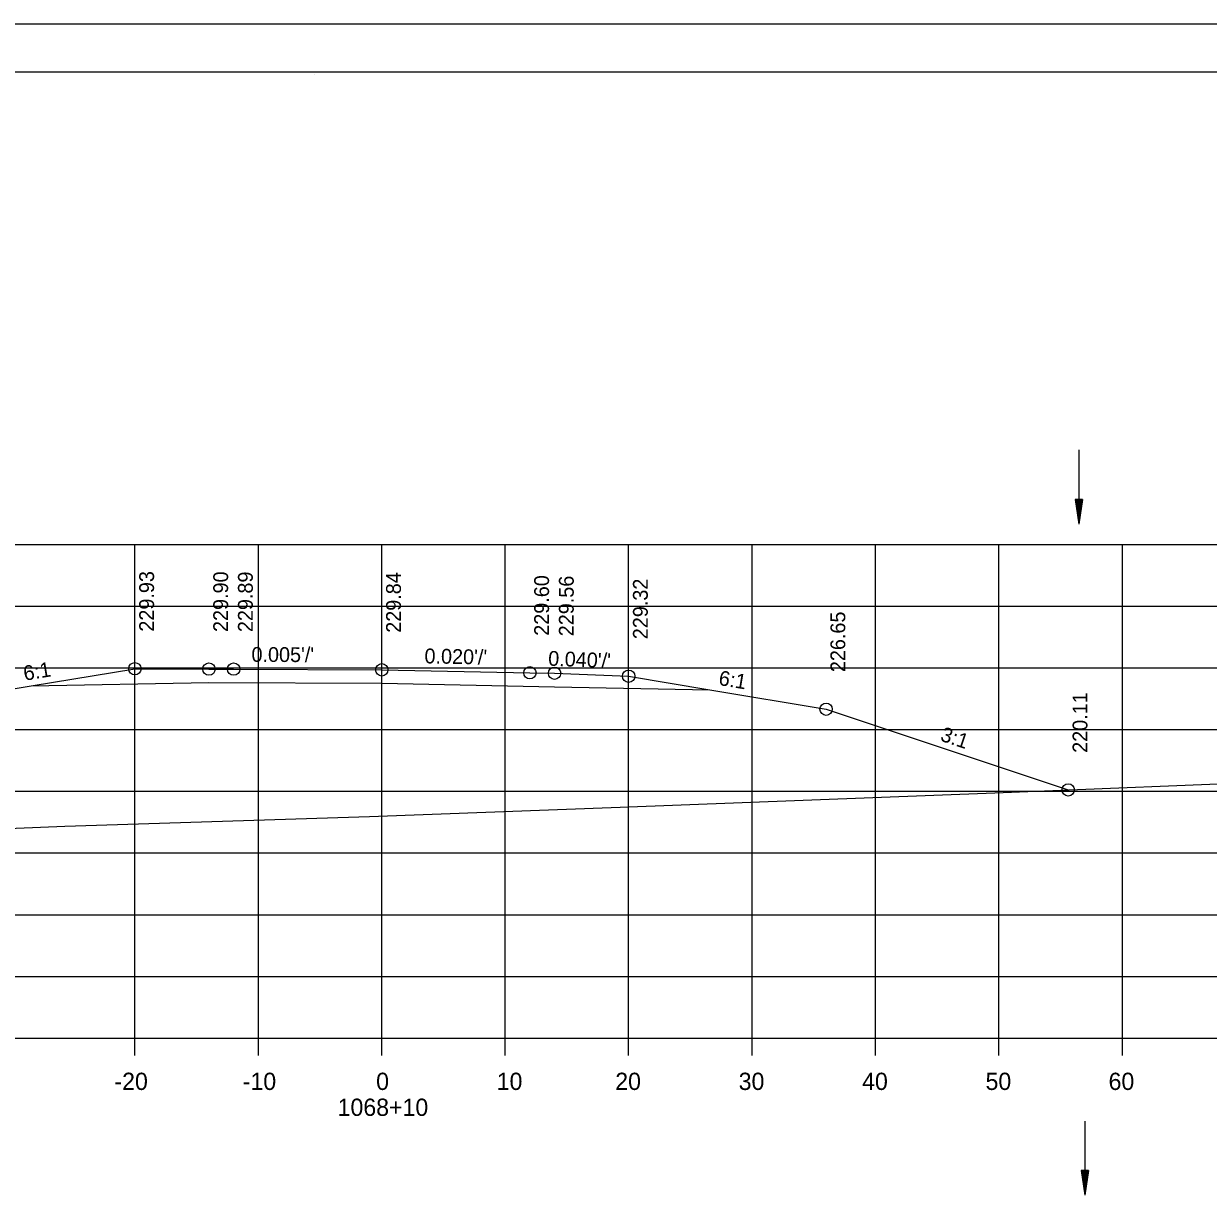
# Model space of a CAD drawing. Extents: x 1386544 to 1388153, y 379785 to 390999.
# Drawn here: x 1387330.7 to 1387426.6, y 389196.4 to 389292.2 of the extents above; entities that cross this region are included whole.
import ezdxf

# ---------------------------------------------------------------- set-up
doc = ezdxf.new("R2010")
doc.units = 0
for name, color, linetype in [('R_Alt Surface', 7, 'Continuous'), ('R_Axis', 7, 'Continuous'), ('R_Axis Annot', 7, 'Continuous'), ('R_Border', 7, 'Continuous'), ('R_Exist Surface', 7, 'Continuous'), ('R_Fin Surface', 7, 'Continuous'), ('R_Grid', 7, 'Continuous'), ('R_No Plot', 7, 'Continuous'), ('R_Water', 7, 'Continuous'), ('R_Xsect Elev', 7, 'Continuous'), ('R_Xsect Slope', 7, 'Continuous')]:
    doc.layers.add(name, color=color, linetype=linetype)

msp = doc.modelspace()

# ---------------------------------------------------------------- linework, layer by layer
at = {"layer": 'R_Alt Surface'}
msp.add_lwpolyline([(1387331.28, 389238.58), (1387345.676, 389238.868), (1387359.676, 389238.802), (1387373.676, 389238.522), (1387386.244, 389238.271)], dxfattribs=at)
at = {"layer": 'R_Axis'}
for p, q in [((1387209.676, 389210.047), (1387509.676, 389210.047)), ((1387339.676, 389208.647), (1387339.676, 389210.047)), ((1387349.676, 389208.647), (1387349.676, 389210.047)), ((1387359.676, 389208.647), (1387359.676, 389210.047)), ((1387369.676, 389208.647), (1387369.676, 389210.047)), ((1387379.676, 389208.647), (1387379.676, 389210.047)), ((1387389.676, 389208.647), (1387389.676, 389210.047)), ((1387399.676, 389208.647), (1387399.676, 389210.047)), ((1387409.676, 389208.647), (1387409.676, 389210.047)), ((1387419.676, 389208.647), (1387419.676, 389210.047))]:
    msp.add_line(p, q, dxfattribs=at)
at = {"layer": 'R_Border'}
for p, q in [((1387201.676, 389288.341), (1387517.856, 389288.341)), ((1387354.196, 389288.081), (1387354.196, 389288.081)), ((1387354.196, 389288.081), (1387354.196, 389288.081))]:
    msp.add_line(p, q, dxfattribs=at)
at = {"layer": 'R_Exist Surface'}
msp.add_lwpolyline([(1387209.676, 389224.983), (1387215.026, 389224.85), (1387226.169, 389224.49), (1387241.258, 389224.328), (1387246.492, 389224.385), (1387256.193, 389224.164), (1387262.552, 389224.427), (1387271.36, 389224.58), (1387283.354, 389223.845), (1387289.212, 389224.003), (1387290.857, 389224.051), (1387299.843, 389225.003), (1387307.761, 389225.911), (1387311.003, 389226.283), (1387333.99, 389227.23), (1387358.675, 389228.01), (1387378.996, 389228.765), (1387409.347, 389229.916), (1387433.447, 389230.903), (1387461.681, 389232.028), (1387502.009, 389233.928), (1387509.676, 389234.295)], dxfattribs=at)
at = {"layer": 'R_Fin Surface'}
msp.add_lwpolyline([(1387283.285, 389223.849), (1387287.887, 389225.386), (1387323.676, 389237.313), (1387331.28, 389238.58), (1387339.676, 389239.979), (1387345.676, 389239.951), (1387347.676, 389239.942), (1387359.676, 389239.886), (1387371.676, 389239.646), (1387373.676, 389239.606), (1387379.676, 389239.366), (1387386.244, 389238.271), (1387395.676, 389236.699), (1387415.293, 389230.16)], dxfattribs=at)
at = {"layer": 'R_Grid'}
for p, q in [((1387209.676, 389250.047), (1387509.676, 389250.047)), ((1387339.676, 389210.047), (1387339.676, 389250.047)), ((1387349.676, 389210.047), (1387349.676, 389250.047)), ((1387359.676, 389210.047), (1387359.676, 389250.047)), ((1387369.676, 389210.047), (1387369.676, 389250.047)), ((1387379.676, 389210.047), (1387379.676, 389250.047)), ((1387389.676, 389210.047), (1387389.676, 389250.047)), ((1387399.676, 389210.047), (1387399.676, 389250.047)), ((1387409.676, 389210.047), (1387409.676, 389250.047)), ((1387419.676, 389210.047), (1387419.676, 389250.047)), ((1387209.676, 389245.047), (1387509.676, 389245.047)), ((1387209.676, 389240.047), (1387509.676, 389240.047)), ((1387209.676, 389235.047), (1387509.676, 389235.047)), ((1387209.676, 389230.047), (1387509.676, 389230.047)), ((1387209.676, 389225.047), (1387509.676, 389225.047)), ((1387209.676, 389220.047), (1387509.676, 389220.047)), ((1387209.676, 389215.047), (1387509.676, 389215.047)), ((1387209.676, 389210.047), (1387509.676, 389210.047))]:
    msp.add_line(p, q, dxfattribs=at)
at = {"layer": 'R_No Plot'}
msp.add_line((1387189.275, 389292.235), (1387522.609, 389292.235), dxfattribs=at)
for points in [[(1387189.269, 389292.235), (1387522.609, 389292.235), (1387522.609, 389078.898), (1387189.269, 389078.898)], [(1387435.596, 389288.341), (1387455.216, 389288.341), (1387455.216, 389278.461), (1387471.328, 389278.461), (1387494.528, 389278.461), (1387494.528, 389254.128), (1387517.856, 389254.128), (1387517.856, 389082.881), (1387201.676, 389082.881), (1387201.676, 389288.341)]]:
    msp.add_lwpolyline(points, close=True, dxfattribs=at)
for centre in [(1387339.676, 389239.979), (1387345.676, 389239.951), (1387347.676, 389239.942), (1387359.676, 389239.886), (1387371.676, 389239.646), (1387373.676, 389239.606), (1387379.676, 389239.366), (1387395.676, 389236.699), (1387415.293, 389230.16)]:
    msp.add_circle(centre, 0.5, dxfattribs=at)
at = {"layer": 'R_Water'}
for p, q in [((1387416.151, 389257.698), (1387416.151, 389251.698)), ((1387415.851, 389253.698), (1387416.151, 389251.698)), ((1387416.451, 389253.698), (1387415.851, 389253.698)), ((1387415.851, 389253.698), (1387416.151, 389251.698)), ((1387416.451, 389253.698), (1387415.851, 389253.698)), ((1387415.901, 389253.698), (1387416.151, 389252.032)), ((1387415.901, 389253.698), (1387416.151, 389252.032)), ((1387415.952, 389253.698), (1387416.151, 389252.376)), ((1387415.952, 389253.698), (1387416.151, 389252.376)), ((1387416.002, 389253.698), (1387416.151, 389252.709)), ((1387416.002, 389253.698), (1387416.151, 389252.709)), ((1387416.053, 389253.698), (1387416.151, 389253.048)), ((1387416.053, 389253.698), (1387416.151, 389253.048)), ((1387416.104, 389253.698), (1387416.151, 389253.382)), ((1387416.104, 389253.698), (1387416.151, 389253.382)), ((1387416.451, 389253.698), (1387416.151, 389251.698)), ((1387416.248, 389253.698), (1387416.151, 389253.048)), ((1387416.35, 389253.698), (1387416.151, 389252.376)), ((1387416.401, 389253.698), (1387416.151, 389252.032)), ((1387416.3, 389253.698), (1387416.151, 389252.709)), ((1387416.198, 389253.698), (1387416.151, 389253.382)), ((1387416.451, 389253.698), (1387416.151, 389251.698)), ((1387416.248, 389253.698), (1387416.151, 389253.048)), ((1387416.35, 389253.698), (1387416.151, 389252.376)), ((1387416.401, 389253.698), (1387416.151, 389252.032)), ((1387416.3, 389253.698), (1387416.151, 389252.709)), ((1387416.198, 389253.698), (1387416.151, 389253.382)), ((1387416.624, 389203.322), (1387416.624, 389197.322)), ((1387416.324, 389199.322), (1387416.624, 389197.322)), ((1387416.924, 389199.322), (1387416.324, 389199.322)), ((1387416.324, 389199.322), (1387416.624, 389197.322)), ((1387416.924, 389199.322), (1387416.324, 389199.322)), ((1387416.374, 389199.322), (1387416.624, 389197.656)), ((1387416.374, 389199.322), (1387416.624, 389197.656)), ((1387416.425, 389199.322), (1387416.624, 389198)), ((1387416.425, 389199.322), (1387416.624, 389198)), ((1387416.475, 389199.322), (1387416.624, 389198.333)), ((1387416.475, 389199.322), (1387416.624, 389198.333)), ((1387416.526, 389199.322), (1387416.624, 389198.672)), ((1387416.526, 389199.322), (1387416.624, 389198.672)), ((1387416.577, 389199.322), (1387416.624, 389199.006)), ((1387416.577, 389199.322), (1387416.624, 389199.006)), ((1387416.924, 389199.322), (1387416.624, 389197.322)), ((1387416.721, 389199.322), (1387416.624, 389198.672)), ((1387416.823, 389199.322), (1387416.624, 389198)), ((1387416.874, 389199.322), (1387416.624, 389197.656)), ((1387416.773, 389199.322), (1387416.624, 389198.333)), ((1387416.671, 389199.322), (1387416.624, 389199.006)), ((1387416.924, 389199.322), (1387416.624, 389197.322)), ((1387416.721, 389199.322), (1387416.624, 389198.672)), ((1387416.823, 389199.322), (1387416.624, 389198)), ((1387416.874, 389199.322), (1387416.624, 389197.656)), ((1387416.773, 389199.322), (1387416.624, 389198.333)), ((1387416.671, 389199.322), (1387416.624, 389199.006))]:
    msp.add_line(p, q, dxfattribs=at)

# ---------------------------------------------------------------- texts
at = {"layer": 'R_Axis Annot'}
for s, p in [('-20', (1387338.017, 389205.847)), ('-10', (1387348.414, 389205.847)), ('0', (1387359.219, 389205.847)), ('10', (1387368.987, 389205.847)), ('20', (1387378.59, 389205.847)), ('30', (1387388.59, 389205.847)), ('40', (1387398.59, 389205.847)), ('50', (1387408.59, 389205.847)), ('60', (1387418.557, 389205.847)), ('1068+10', (1387356.099, 389203.747))]:
    msp.add_text(s, height=1.4, dxfattribs=at).set_placement(p)
at = {"layer": 'R_Xsect Elev'}
for s, p in [('229.93', (1387341.226, 389242.979)), ('229.90', (1387347.226, 389242.951)), ('229.89', (1387349.226, 389242.942)), ('229.84', (1387361.226, 389242.886)), ('229.60', (1387373.226, 389242.646)), ('229.56', (1387375.226, 389242.606)), ('229.32', (1387381.226, 389242.366)), ('226.65', (1387397.226, 389239.699)), ('220.11', (1387416.843, 389233.16))]:
    msp.add_text(s, height=1.2, rotation=90, dxfattribs=at).set_placement(p)
at = {"layer": 'R_Xsect Slope'}
for s, rotation, p in [("0.005'/'", 359.73103, (1387349.117, 389240.535)), ("0.020'/'", 358.85424, (1387363.127, 389240.417)), ("0.040'/'", 357.70939, (1387373.141, 389240.227)), ('6:1', 9.46232, (1387330.746, 389238.998)), ('6:1', 350.53768, (1387386.91, 389238.667)), ('3:1', 341.56507, (1387404.854, 389234.167))]:
    msp.add_text(s, height=1.2, rotation=rotation, dxfattribs=at).set_placement(p)

doc.saveas('drawing.dxf')
